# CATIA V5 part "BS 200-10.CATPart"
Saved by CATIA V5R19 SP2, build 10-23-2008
Part number: BS 200-10
Bounding box of the stored display mesh (mm): x -12.497 to 12.497, y -12.358 to 12.358, z 0 to 50
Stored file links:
  C:\Users\Bora\Desktop\3D Katı model\BS serisi\BS 200\BS 200-10.CATPart
  C:\Program Files\Dassault Systemes\B19\intel_a\reffiles\standard\MetricThickPitch.txt
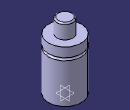
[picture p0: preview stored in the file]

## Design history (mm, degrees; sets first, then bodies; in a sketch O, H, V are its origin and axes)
Body1 (main body)
  Sketch1 on yz-plane, origin (0, 0, 0), H (0, 1, 0), V (0, 0, 1)
    point P1 (6, 49)
    point P3 (6, 49)
    point P5 (12.5, 32)
    point P6 (12.5, 30)
    point P8 (12.5, 30)
    point P9 (12.5, 32)
    line L1 (6, 49) -> (6, 39)
    arc A1 centre (5, 49) radius 1 from (6, 49) to (5, 50) ccw
    arc A2 centre (12.5, 31) radius 1 from (12.5, 32) to (12.5, 30) ccw
    line L2 (12.5, 0) -> (12.5, 30)
    line L3 (12.5, 32) -> (12.5, 39)
    line L4 (5, 50) -> (0, 50)
    point P11 (0, 50)
    line L5 (6, 39) -> (12.5, 39)
    line L6 (12.5, 0) -> (0, 0)
    coincidence: P11 V, P1 P3, P5 P9, P6 P8
    tangency: L4 A1
    horizontal: L5 H, L6 H
  Shaft1: profile Sketch1, axis Sketch1.V, angle 360
  Sketch2 on face of Shaft1 from Sketch1.L6, origin (0, 0, 0), H (1, 0, 0), V (0, -1, 0)
    point P1 (0, 0)
  Hole1: placed by Sketch2, at (0, 0, 0) direction (0, 0, 1), diameter 4.917, depth 4, threaded "M6", thread diameter 6, thread depth 4, pitch 1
